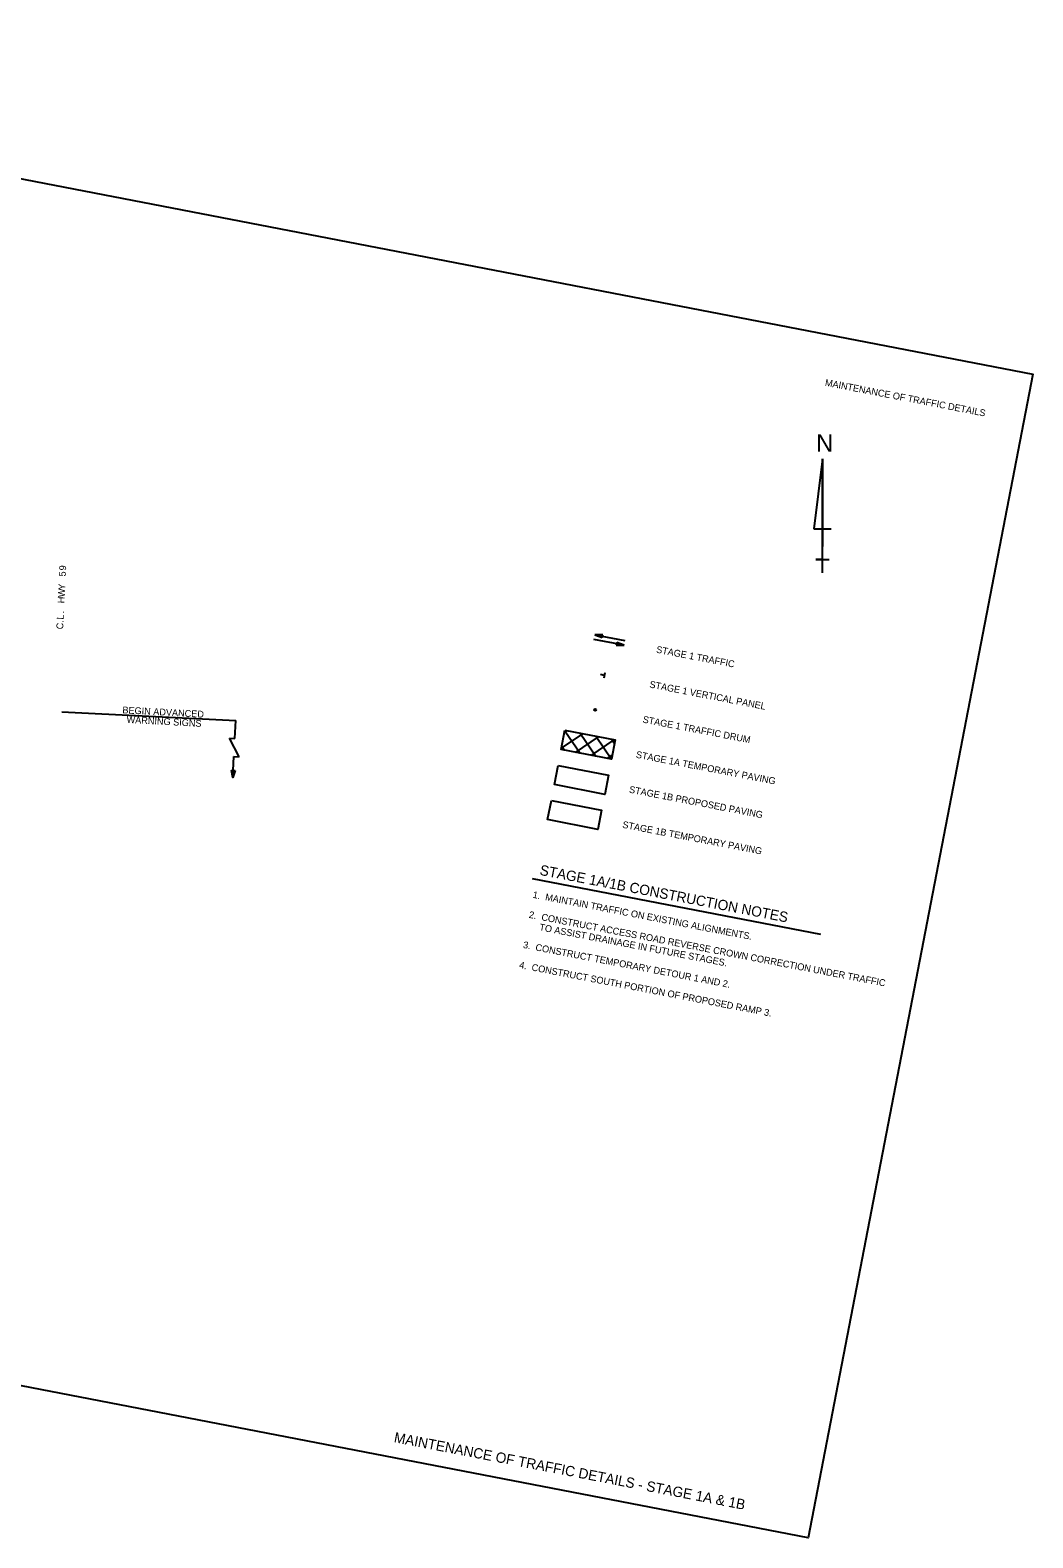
# Model space of a CAD drawing. Extents: x 609776 to 611540, y 418046 to 419372.
# Drawn here: x 610658 to 611540, y 418046 to 419372 of the extents above; entities that cross this region are included whole.
import ezdxf

# ---------------------------------------------------------------- set-up
doc = ezdxf.new("R2010")
doc.units = 0
for name, color, linetype in [('G-ANNO-TEXT', 7, 'Continuous'), ('G-Border-Sheet', 7, 'Continuous'), ('Level 1', 7, 'Continuous'), ('Level 3', 7, 'Continuous'), ('Level 47', 7, 'Continuous'), ('Level 62', 7, 'Continuous'), ('R_Draft', 7, 'Continuous')]:
    doc.layers.add(name, color=color, linetype=linetype)

msp = doc.modelspace()

# ---------------------------------------------------------------- linework, layer by layer
at = {"layer": 'G-Border-Sheet'}
msp.add_lwpolyline([(609973.3, 419372.2), (611539.8, 419069.8), (611342.2, 418046.4), (609775.8, 418348.8)], close=True, dxfattribs=at)
at = {"layer": 'Level 1'}
for p, q in [((611354.8, 418995.1), (611347.1, 418933.6)), ((611354.8, 418895.1), (611354.8, 418995.1)), ((611354.8, 418995.1), (611354.8, 418918.2)), ((611347.1, 418933.6), (611362.5, 418933.6)), ((611354.8, 418895.1), (611354.8, 418918.2)), ((611354.8, 418906.6), (611349, 418906.6)), ((611349, 418906.6), (611360.6, 418906.6)), ((611354.8, 418895.1), (611354.8, 418906.6))]:
    msp.add_line(p, q, dxfattribs=at)
at = {"layer": 'Level 3'}
for p, q in [((611163.3, 418807.2), (611162.4, 418802.3)), ((611162.8, 418804.8), (611159.4, 418805.5))]:
    msp.add_line(p, q, dxfattribs=at)
at = {"layer": 'Level 47'}
msp.add_circle((611154.8, 418774.5), 1, dxfattribs=at)
at = {"layer": 'Level 62'}
for p, q in [((611180.2, 418831.3), (611153.7, 418836.3)), ((611161.4, 418840.5), (611154.5, 418840.6)), ((611154.5, 418840.6), (611160.9, 418838.2)), ((611154.5, 418840.6), (611181, 418835.5)), ((611156.2, 418840.1), (611161, 418838.7)), ((611161.3, 418839.9), (611156.3, 418840.4)), ((611160.9, 418838.2), (611161.4, 418840.5)), ((611173.8, 418833.7), (611173.3, 418831.4)), ((611180.2, 418831.3), (611173.8, 418833.7)), ((611173.3, 418831.4), (611180.2, 418831.3)), ((611173.4, 418832), (611178.4, 418831.4)), ((611178.5, 418831.7), (611173.7, 418833.1))]:
    msp.add_line(p, q, dxfattribs=at)
at = {"layer": 'R_Draft'}
for p, q in [((610685.7, 418772.9), (610838.7, 418765.1)), ((610837.9, 418749.4), (610838.7, 418765.1)), ((611127.8, 418754.8), (611129.9, 418756.2)), ((611128.1, 418756.2), (611141.5, 418736.4)), ((611141.7, 418753.9), (611155.4, 418733.7)), ((610841.7, 418733.2), (610833.2, 418749.6)), ((610833.2, 418749.6), (610837.7, 418749.4)), ((611125.1, 418740.9), (611143.8, 418753.5)), ((611125.4, 418742.3), (611127.6, 418739)), ((611137.4, 418737.1), (611157.6, 418750.8)), ((611151.3, 418734.5), (611171.5, 418748.1)), ((611155.6, 418751.2), (611169.2, 418731.1)), ((611169.5, 418748.5), (611171.8, 418745)), ((610836.2, 418715.1), (610837.1, 418733.4)), ((610837.1, 418733.4), (610841.7, 418733.2)), ((611165.2, 418731.8), (611169.9, 418735))]:
    msp.add_line(p, q, dxfattribs=at)
for points in [[(611128.1, 418756.5), (611172.4, 418748), (611169.1, 418731), (611124.9, 418739.6)], [(610838, 418721.1), (610836.2, 418715.1), (610835, 418721.2)], [(611122.2, 418725.7), (611166.5, 418717.2), (611163.2, 418700.2), (611118.9, 418708.8)], [(611116.3, 418694.9), (611160.5, 418686.4), (611157.2, 418669.4), (611113, 418678)]]:
    msp.add_lwpolyline(points, close=True, dxfattribs=at)
msp.add_lwpolyline([(611353.2, 418577.1), (611099.7, 418626)], dxfattribs=at)
msp.add_lwpolyline([(611353.2, 418577.1), (611099.7, 418626)], dxfattribs=at)

# ---------------------------------------------------------------- texts
at = {"layer": 'G-ANNO-TEXT'}
for s, height, p in [('MAINTENANCE OF TRAFFIC DETAILS', 6, (611356.6, 419059.6)), ('MAINTENANCE OF TRAFFIC DETAILS - STAGE 1A & 1B', 9, (610977.3, 418130.6))]:
    msp.add_text(s, height=height, rotation=349.0745, dxfattribs=at).set_placement(p)
at = {"layer": 'Level 1'}
msp.add_text('N', height=15.4, rotation=360, dxfattribs=at).set_placement((611349.2, 419001.5))
at = {"layer": 'R_Draft'}
for s, height, rotation, p in [('9', 6, 87.2386, (610689.3, 418897)), ('5', 6, 87.2386, (610689, 418891.7)), ('H', 6, 87.2386, (610687.9, 418868.1)), ('W', 6, 87.2386, (610688.2, 418873.5)), ('Y', 6, 87.2386, (610688.5, 418879.9)), ('.', 6, 87.2386, (610687.5, 418859.2)), ('C', 6, 87.2386, (610686.8, 418845.2)), ('L', 6, 87.2386, (610687.2, 418853.8)), ('.', 6, 87.2386, (610687.1, 418850.9)), ('STAGE 1 TRAFFIC', 6, 349.0745, (611208.1, 418824.9)), ('STAGE 1 VERTICAL PANEL', 6, 349.0745, (611202.2, 418794.2)), ('BEGIN ADVANCED ', 6, 356.8692, (610738.8, 418771.5)), ('WARNING SIGNS', 6, 356.8692, (610742.5, 418763.1)), ('STAGE 1 TRAFFIC DRUM', 6, 349.0745, (611196.2, 418763.4)), ('STAGE 1A TEMPORARY PAVING', 6, 349.0745, (611190.3, 418732.5)), ('STAGE 1B PROPOSED PAVING', 6, 349.0745, (611184.3, 418701.8)), ('STAGE 1B TEMPORARY PAVING', 6, 349.0745, (611178.4, 418670.9)), ('STAGE 1A/1B CONSTRUCTION NOTES', 9, 349.0919, (611105.5, 418629.5)), ('1. ', 6, 349.0745, (611099.5, 418609.3)), ('MAINTAIN TRAFFIC ON EXISTING ALIGNMENTS.', 6, 349.0745, (611110.5, 418607.2)), ('2. ', 6, 349.0745, (611096.1, 418591.7)), ('CONSTRUCT ACCESS ROAD REVERSE CROWN CORRECTION UNDER TRAFFIC ', 6, 349.0745, (611107.1, 418589.6)), ('TO ASSIST DRAINAGE IN FUTURE STAGES.', 6, 349.0745, (611105.3, 418580.7)), ('3.', 6, 349.0745, (611091, 418565.2)), ('CONSTRUCT TEMPORARY DETOUR 1 AND 2.', 6, 349.0745, (611101.9, 418563)), ('4.', 6, 349.0745, (611087.6, 418547.5)), ('CONSTRUCT SOUTH PORTION OF PROPOSED RAMP 3.', 6, 349.0745, (611098.5, 418545.4))]:
    msp.add_text(s, height=height, rotation=rotation, dxfattribs=at).set_placement(p)

doc.saveas('drawing.dxf')
